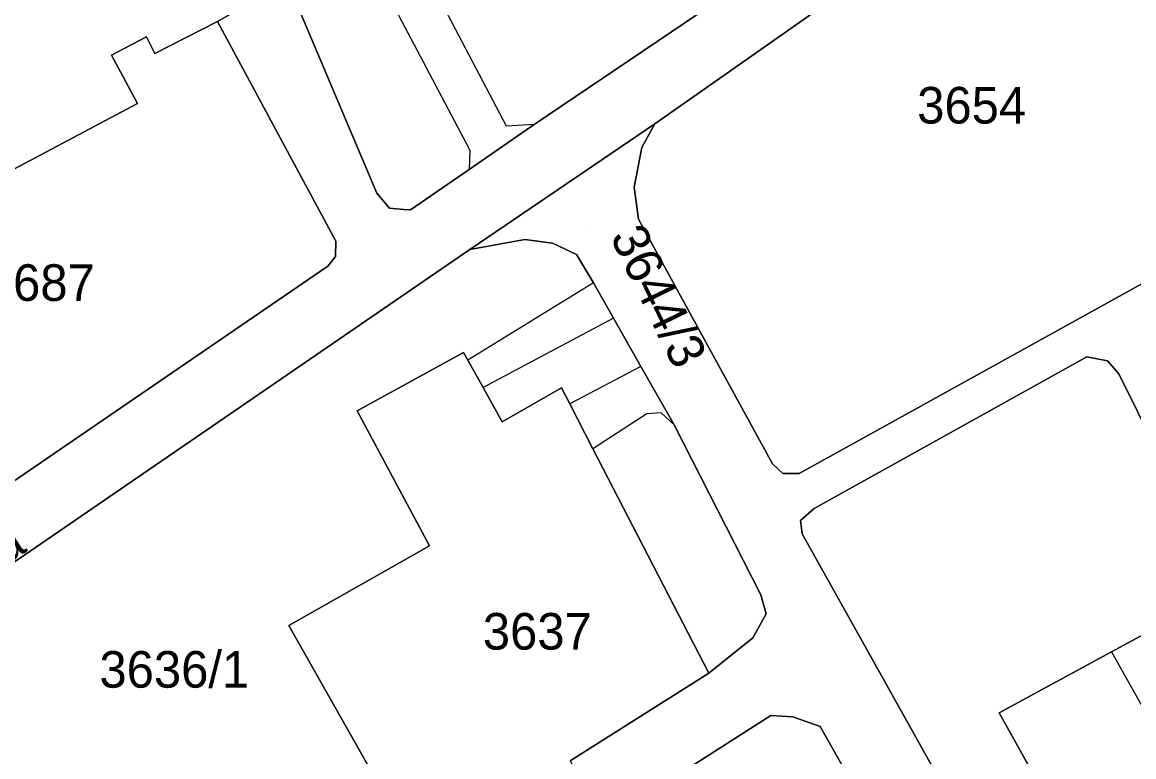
# Model space of a CAD drawing. Extents: x -262715 to -259381, y -1237238 to -1231182.
# Drawn here: x -261788.7 to -261728, y -1235759.3 to -1235719.2 of the extents above; entities that cross this region are included whole.
import ezdxf

# ---------------------------------------------------------------- set-up
doc = ezdxf.new("R2010")
doc.units = 0
for name, color, linetype in [('body_kn', 7, 'Continuous'), ('kladpar_druhypozemkov', 7, 'Continuous'), ('kladpar_hranice', 7, 'Continuous'), ('kladpar_parcelnecisla', 7, 'Continuous'), ('kladpar_plochy', 7, 'Continuous'), ('popisy', 7, 'Continuous'), ('zappar_hrandruhpozemk', 7, 'Continuous')]:
    doc.layers.add(name, color=color, linetype=linetype)

msp = doc.modelspace()

# ---------------------------------------------------------------- linework, layer by layer
at = {"layer": 'body_kn'}
for p, q in [((-261781.92, -1235719.95), (-261781.92, -1235719.95)), ((-261781.45, -1235720.86), (-261781.45, -1235720.86)), ((-261783.82, -1235720.96), (-261783.82, -1235720.96)), ((-261782.41, -1235723.59), (-261782.41, -1235723.59)), ((-261762.25, -1235724.84), (-261762.25, -1235724.84)), ((-261760.74, -1235724.75), (-261760.74, -1235724.75)), ((-261760.74, -1235724.75), (-261760.74, -1235724.75)), ((-261754.15, -1235724.7), (-261754.15, -1235724.7)), ((-261754.15, -1235724.7), (-261754.15, -1235724.7)), ((-261764.26, -1235726.15), (-261764.26, -1235726.15)), ((-261754.87, -1235726), (-261754.87, -1235726)), ((-261764.3, -1235727.21), (-261764.3, -1235727.21)), ((-261755.29, -1235728.17), (-261755.29, -1235728.17)), ((-261769.34, -1235728.5), (-261769.34, -1235728.5)), ((-261768.64, -1235729.32), (-261768.64, -1235729.32)), ((-261767.88, -1235729.38), (-261767.88, -1235729.38)), ((-261767.49, -1235729.41), (-261767.49, -1235729.41)), ((-261755.05, -1235729.92), (-261755.05, -1235729.92)), ((-261771.57, -1235731.11), (-261771.57, -1235731.11)), ((-261761.25, -1235731.03), (-261761.25, -1235731.03)), ((-261764.25, -1235731.57), (-261764.25, -1235731.57)), ((-261759.74, -1235731.22), (-261759.74, -1235731.22)), ((-261771.6, -1235731.95), (-261771.6, -1235731.95)), ((-261758.44, -1235731.84), (-261758.44, -1235731.84)), ((-261772.02, -1235732.49), (-261772.02, -1235732.49)), ((-261757.51, -1235733.39), (-261757.51, -1235733.39)), ((-261757.51, -1235733.39), (-261757.51, -1235733.39)), ((-261756.41, -1235735.32), (-261756.41, -1235735.32)), ((-261756.41, -1235735.32), (-261756.41, -1235735.32)), ((-261764.6, -1235737.19), (-261764.6, -1235737.19)), ((-261764.6, -1235737.19), (-261764.6, -1235737.19)), ((-261764.36, -1235737.62), (-261764.36, -1235737.62)), ((-261730.57, -1235737.43), (-261730.57, -1235737.43)), ((-261729.44, -1235737.66), (-261729.44, -1235737.66)), ((-261754.91, -1235737.97), (-261754.91, -1235737.97)), ((-261754.91, -1235737.97), (-261754.91, -1235737.97)), ((-261728.81, -1235738.36), (-261728.81, -1235738.36)), ((-261763.53, -1235739.11), (-261763.53, -1235739.11)), ((-261759.26, -1235739.13), (-261759.26, -1235739.13)), ((-261758.8, -1235740.01), (-261758.8, -1235740.01)), ((-261770.41, -1235740.39), (-261770.41, -1235740.39)), ((-261754.59, -1235740.55), (-261754.59, -1235740.55)), ((-261753.8, -1235740.5), (-261753.8, -1235740.5)), ((-261762.5, -1235740.98), (-261762.5, -1235740.98)), ((-261753.1, -1235741.15), (-261753.1, -1235741.15)), ((-261753.1, -1235741.15), (-261753.1, -1235741.15)), ((-261757.54, -1235742.46), (-261757.54, -1235742.46)), ((-261747.72, -1235743.29), (-261747.72, -1235743.29)), ((-261747.17, -1235743.8), (-261747.17, -1235743.8)), ((-261746.28, -1235743.8), (-261746.28, -1235743.8)), ((-261745.46, -1235745.72), (-261745.46, -1235745.72)), ((-261746.2, -1235746.37), (-261746.2, -1235746.37)), ((-261746.1, -1235747.11), (-261746.1, -1235747.11)), ((-261766.46, -1235747.76), (-261766.46, -1235747.76)), ((-261748.36, -1235750.44), (-261748.36, -1235750.44)), ((-261748.08, -1235751.48), (-261748.08, -1235751.48)), ((-261774.14, -1235752.11), (-261774.14, -1235752.11)), ((-261748.8, -1235752.78), (-261748.8, -1235752.78)), ((-261729.21, -1235753.55), (-261729.21, -1235753.55)), ((-261729.21, -1235753.55), (-261729.21, -1235753.55)), ((-261751.21, -1235754.71), (-261751.21, -1235754.71)), ((-261751.21, -1235754.71), (-261751.21, -1235754.71)), ((-261747.82, -1235757.03), (-261747.82, -1235757.03)), ((-261746.62, -1235757.1), (-261746.62, -1235757.1)), ((-261735.35, -1235756.88), (-261735.35, -1235756.88)), ((-261745.12, -1235757.63), (-261745.12, -1235757.63))]:
    msp.add_line(p, q, dxfattribs=at)
at = {"layer": 'kladpar_druhypozemkov'}
for p, q in [((-261736.65, -1235722.84), (-261736.65, -1235722.84)), ((-261757.99, -1235730.49), (-261757.99, -1235730.49)), ((-261787.49, -1235732.36), (-261787.49, -1235732.36)), ((-261759.9, -1235751.2), (-261759.9, -1235751.2)), ((-261780.12, -1235753.85), (-261780.12, -1235753.85))]:
    msp.add_line(p, q, dxfattribs=at)
at = {"layer": 'kladpar_hranice'}
for points in [[(-261717.12, -1235627), (-261717.4, -1235648.09), (-261717.59, -1235653.98), (-261717.84, -1235663.64), (-261718.13, -1235676.23), (-261719.51, -1235683.85), (-261721.57, -1235689.6), (-261724.9, -1235697.03), (-261727.66, -1235701.46), (-261730.28, -1235705), (-261736.14, -1235711.04), (-261740.93, -1235715.41), (-261754.15, -1235724.7), (-261764.25, -1235731.57), (-261797.34, -1235754.27)], [(-261789.32, -1235744.33), (-261772.02, -1235732.49), (-261771.6, -1235731.95), (-261771.57, -1235731.11), (-261778.03, -1235719.11), (-261774.4, -1235717.04), (-261773.56, -1235718.52), (-261769.34, -1235728.5), (-261768.64, -1235729.32), (-261767.88, -1235729.38), (-261767.49, -1235729.41), (-261764.3, -1235727.21), (-261760.74, -1235724.75), (-261750.28, -1235717.66), (-261746.09, -1235714.82), (-261743.34, -1235712.7), (-261738.81, -1235708.72), (-261732.7, -1235702.38), (-261728.83, -1235696.49), (-261726.07, -1235688.93)], [(-261730.28, -1235705), (-261722.76, -1235717.48), (-261717.28, -1235728.03), (-261724.17, -1235731.57), (-261746.28, -1235743.8), (-261747.17, -1235743.8), (-261747.72, -1235743.29), (-261755.05, -1235729.92), (-261755.29, -1235728.17), (-261754.87, -1235726), (-261754.15, -1235724.7), (-261740.93, -1235715.41), (-261736.14, -1235711.04), (-261730.28, -1235705)], [(-261791.19, -1235707.6), (-261790.03, -1235709.7), (-261784.69, -1235706.75), (-261783.79, -1235708.37), (-261780.06, -1235706.41), (-261779.54, -1235707.38), (-261774.4, -1235717.04), (-261778.03, -1235719.11), (-261781.45, -1235720.86), (-261781.92, -1235719.95), (-261783.82, -1235720.96), (-261782.41, -1235723.59), (-261790.93, -1235728.12), (-261799.6, -1235712.11), (-261791.19, -1235707.6)], [(-261778.03, -1235719.11), (-261771.57, -1235731.11), (-261771.6, -1235731.95), (-261772.02, -1235732.49), (-261789.32, -1235744.33), (-261790.33, -1235744.3), (-261790.91, -1235743.76), (-261806.68, -1235712.69), (-261805.76, -1235710.7), (-261804.47, -1235709.16), (-261802.05, -1235713.55), (-261799.6, -1235712.11), (-261790.93, -1235728.12), (-261782.41, -1235723.59), (-261783.82, -1235720.96), (-261781.92, -1235719.95), (-261781.45, -1235720.86), (-261778.03, -1235719.11)], [(-261750.28, -1235717.66), (-261760.74, -1235724.75), (-261764.3, -1235727.21), (-261767.49, -1235729.41), (-261767.88, -1235729.38), (-261768.64, -1235729.32), (-261769.34, -1235728.5), (-261773.56, -1235718.52)], [(-261758.78, -1235759.5), (-261751.21, -1235754.71), (-261748.8, -1235752.78), (-261748.08, -1235751.48), (-261748.36, -1235750.44), (-261753.1, -1235741.15), (-261754.91, -1235737.97), (-261756.41, -1235735.32), (-261757.51, -1235733.39), (-261758.44, -1235731.84), (-261759.74, -1235731.22), (-261761.25, -1235731.03), (-261764.25, -1235731.57), (-261754.15, -1235724.7)], [(-261754.15, -1235724.7), (-261754.87, -1235726), (-261755.29, -1235728.17), (-261755.05, -1235729.92), (-261747.72, -1235743.29), (-261747.17, -1235743.8), (-261746.28, -1235743.8), (-261724.17, -1235731.57), (-261717.28, -1235728.03), (-261716.2, -1235730.01), (-261723.1, -1235733.74), (-261726.07, -1235735.35), (-261726.53, -1235736.18), (-261726.41, -1235736.84), (-261722.55, -1235743.22), (-261725.61, -1235744.82), (-261728.81, -1235738.36), (-261729.44, -1235737.66), (-261730.57, -1235737.43), (-261745.46, -1235745.72), (-261746.2, -1235746.37), (-261746.1, -1235747.11), (-261697.33, -1235834.41)], [(-261797.34, -1235754.27), (-261764.25, -1235731.57), (-261761.25, -1235731.03), (-261759.74, -1235731.22), (-261758.44, -1235731.84), (-261757.51, -1235733.39), (-261756.41, -1235735.32), (-261754.91, -1235737.97), (-261753.1, -1235741.15), (-261748.36, -1235750.44), (-261748.08, -1235751.48), (-261748.8, -1235752.78), (-261751.21, -1235754.71)], [(-261751.21, -1235754.71), (-261757.54, -1235742.46), (-261758.8, -1235740.01), (-261759.26, -1235739.13), (-261762.5, -1235740.98), (-261763.53, -1235739.11), (-261764.36, -1235737.62), (-261764.6, -1235737.19), (-261770.41, -1235740.39), (-261766.46, -1235747.76), (-261774.14, -1235752.11), (-261765.37, -1235767.62)], [(-261764.6, -1235737.19), (-261764.36, -1235737.62), (-261763.53, -1235739.11), (-261762.5, -1235740.98), (-261759.26, -1235739.13), (-261758.8, -1235740.01), (-261757.54, -1235742.46), (-261751.21, -1235754.71), (-261758.78, -1235759.5), (-261756.9, -1235762.83), (-261765.37, -1235767.62), (-261774.14, -1235752.11), (-261766.46, -1235747.76), (-261770.41, -1235740.39), (-261764.6, -1235737.19)], [(-261725.61, -1235744.82), (-261727.44, -1235752.59), (-261729.21, -1235753.55), (-261735.35, -1235756.88), (-261699.94, -1235820.45), (-261693.78, -1235817.07), (-261687.54, -1235813.73), (-261684.67, -1235818.85), (-261683.91, -1235820.21), (-261680.97, -1235825.29), (-261680.7, -1235826.01), (-261681.15, -1235826.78), (-261695.73, -1235835.01), (-261696.66, -1235835.19), (-261697.33, -1235834.41), (-261746.1, -1235747.11), (-261746.2, -1235746.37), (-261745.46, -1235745.72), (-261730.57, -1235737.43), (-261729.44, -1235737.66), (-261728.81, -1235738.36), (-261725.61, -1235744.82)], [(-261699.94, -1235820.45), (-261735.35, -1235756.88), (-261729.21, -1235753.55), (-261727.44, -1235752.59), (-261725.61, -1235744.82), (-261722.55, -1235743.22), (-261719.9, -1235741.83), (-261711.44, -1235758.07), (-261706.32, -1235755.4), (-261707.75, -1235752.48), (-261705.09, -1235751.27), (-261696.75, -1235746.72), (-261697.71, -1235744.96), (-261692.22, -1235742.13)], [(-261765.37, -1235767.62), (-261756.9, -1235762.83), (-261747.82, -1235757.03), (-261746.62, -1235757.1), (-261745.12, -1235757.63), (-261691.44, -1235852.69), (-261691.06, -1235854.65), (-261691.29, -1235856.33), (-261693.25, -1235858.5), (-261692.1, -1235852.85), (-261741.24, -1235766.77), (-261759.23, -1235777.31), (-261765.37, -1235767.62)], [(-261691.44, -1235852.69), (-261745.12, -1235757.63), (-261746.62, -1235757.1), (-261747.82, -1235757.03), (-261756.9, -1235762.83)]]:
    msp.add_lwpolyline(points, dxfattribs=at)
at = {"layer": 'kladpar_plochy'}
for points in [[(-261717.12, -1235627), (-261717.4, -1235648.09), (-261717.59, -1235653.98), (-261717.84, -1235663.64), (-261718.13, -1235676.23), (-261719.51, -1235683.85), (-261721.57, -1235689.6), (-261724.9, -1235697.03), (-261727.66, -1235701.46), (-261730.28, -1235705), (-261736.14, -1235711.04), (-261740.93, -1235715.41), (-261754.15, -1235724.7), (-261764.25, -1235731.57), (-261797.34, -1235754.27)], [(-261789.32, -1235744.33), (-261772.02, -1235732.49), (-261771.6, -1235731.95), (-261771.57, -1235731.11), (-261778.03, -1235719.11), (-261774.4, -1235717.04), (-261773.56, -1235718.52), (-261769.34, -1235728.5), (-261768.64, -1235729.32), (-261767.88, -1235729.38), (-261767.49, -1235729.41), (-261764.3, -1235727.21), (-261760.74, -1235724.75), (-261750.28, -1235717.66), (-261746.09, -1235714.82), (-261743.34, -1235712.7), (-261738.81, -1235708.72), (-261732.7, -1235702.38), (-261728.83, -1235696.49), (-261726.07, -1235688.93)], [(-261750.28, -1235717.66), (-261760.74, -1235724.75), (-261764.3, -1235727.21), (-261767.49, -1235729.41), (-261767.88, -1235729.38), (-261768.64, -1235729.32), (-261769.34, -1235728.5), (-261773.56, -1235718.52)], [(-261758.78, -1235759.5), (-261751.21, -1235754.71), (-261748.8, -1235752.78), (-261748.08, -1235751.48), (-261748.36, -1235750.44), (-261753.1, -1235741.15), (-261754.91, -1235737.97), (-261756.41, -1235735.32), (-261757.51, -1235733.39), (-261758.44, -1235731.84), (-261759.74, -1235731.22), (-261761.25, -1235731.03), (-261764.25, -1235731.57), (-261754.15, -1235724.7), (-261754.87, -1235726), (-261755.29, -1235728.17), (-261755.05, -1235729.92), (-261747.72, -1235743.29), (-261747.17, -1235743.8), (-261746.28, -1235743.8), (-261724.17, -1235731.57)], [(-261797.34, -1235754.27), (-261764.25, -1235731.57), (-261761.25, -1235731.03), (-261759.74, -1235731.22), (-261758.44, -1235731.84), (-261757.51, -1235733.39), (-261756.41, -1235735.32), (-261754.91, -1235737.97), (-261753.1, -1235741.15), (-261748.36, -1235750.44), (-261748.08, -1235751.48), (-261748.8, -1235752.78), (-261751.21, -1235754.71), (-261757.54, -1235742.46), (-261758.8, -1235740.01), (-261759.26, -1235739.13), (-261762.5, -1235740.98), (-261763.53, -1235739.11), (-261764.36, -1235737.62), (-261764.6, -1235737.19), (-261770.41, -1235740.39), (-261766.46, -1235747.76), (-261774.14, -1235752.11), (-261765.37, -1235767.62)], [(-261725.61, -1235744.82), (-261728.81, -1235738.36), (-261729.44, -1235737.66), (-261730.57, -1235737.43), (-261745.46, -1235745.72), (-261746.2, -1235746.37), (-261746.1, -1235747.11), (-261697.33, -1235834.41)], [(-261699.94, -1235820.45), (-261735.35, -1235756.88), (-261729.21, -1235753.55), (-261727.44, -1235752.59), (-261725.61, -1235744.82), (-261722.55, -1235743.22), (-261719.9, -1235741.83), (-261711.44, -1235758.07), (-261706.32, -1235755.4), (-261707.75, -1235752.48), (-261705.09, -1235751.27), (-261696.75, -1235746.72), (-261697.71, -1235744.96), (-261692.22, -1235742.13), (-261691.31, -1235743.76), (-261688.29, -1235749.41), (-261684.3, -1235756.86), (-261675.54, -1235752.17), (-261676.2, -1235750.94), (-261674.29, -1235749.92), (-261673.63, -1235751.15), (-261657.74, -1235742.65), (-261645.58, -1235763.47)], [(-261691.44, -1235852.69), (-261745.12, -1235757.63), (-261746.62, -1235757.1), (-261747.82, -1235757.03), (-261756.9, -1235762.83)]]:
    msp.add_lwpolyline(points, dxfattribs=at)
for points in [[(-261730.28, -1235705), (-261722.76, -1235717.48), (-261717.28, -1235728.03), (-261724.17, -1235731.57), (-261746.28, -1235743.8), (-261747.17, -1235743.8), (-261747.72, -1235743.29), (-261755.05, -1235729.92), (-261755.29, -1235728.17), (-261754.87, -1235726), (-261754.15, -1235724.7), (-261740.93, -1235715.41), (-261736.14, -1235711.04)], [(-261791.19, -1235707.6), (-261790.03, -1235709.7), (-261784.69, -1235706.75), (-261783.79, -1235708.37), (-261780.06, -1235706.41), (-261779.54, -1235707.38), (-261774.4, -1235717.04), (-261778.03, -1235719.11), (-261781.45, -1235720.86), (-261781.92, -1235719.95), (-261783.82, -1235720.96), (-261782.41, -1235723.59), (-261790.93, -1235728.12), (-261799.6, -1235712.11)], [(-261778.03, -1235719.11), (-261771.57, -1235731.11), (-261771.6, -1235731.95), (-261772.02, -1235732.49), (-261789.32, -1235744.33), (-261790.33, -1235744.3), (-261790.91, -1235743.76), (-261806.68, -1235712.69), (-261805.76, -1235710.7), (-261804.47, -1235709.16), (-261802.05, -1235713.55), (-261799.6, -1235712.11), (-261790.93, -1235728.12), (-261782.41, -1235723.59), (-261783.82, -1235720.96), (-261781.92, -1235719.95), (-261781.45, -1235720.86)], [(-261764.6, -1235737.19), (-261764.36, -1235737.62), (-261763.53, -1235739.11), (-261762.5, -1235740.98), (-261759.26, -1235739.13), (-261758.8, -1235740.01), (-261757.54, -1235742.46), (-261751.21, -1235754.71), (-261758.78, -1235759.5), (-261756.9, -1235762.83), (-261765.37, -1235767.62), (-261774.14, -1235752.11), (-261766.46, -1235747.76), (-261770.41, -1235740.39)], [(-261725.61, -1235744.82), (-261727.44, -1235752.59), (-261729.21, -1235753.55), (-261735.35, -1235756.88), (-261699.94, -1235820.45), (-261693.78, -1235817.07), (-261687.54, -1235813.73), (-261684.67, -1235818.85), (-261683.91, -1235820.21), (-261680.97, -1235825.29), (-261680.7, -1235826.01), (-261681.15, -1235826.78), (-261695.73, -1235835.01), (-261696.66, -1235835.19), (-261697.33, -1235834.41), (-261746.1, -1235747.11), (-261746.2, -1235746.37), (-261745.46, -1235745.72), (-261730.57, -1235737.43), (-261729.44, -1235737.66), (-261728.81, -1235738.36)], [(-261765.37, -1235767.62), (-261756.9, -1235762.83), (-261747.82, -1235757.03), (-261746.62, -1235757.1), (-261745.12, -1235757.63), (-261691.44, -1235852.69), (-261691.06, -1235854.65), (-261691.29, -1235856.33), (-261693.25, -1235858.5), (-261692.1, -1235852.85), (-261741.24, -1235766.77), (-261759.23, -1235777.31)]]:
    msp.add_lwpolyline(points, close=True, dxfattribs=at)
at = {"layer": 'zappar_hrandruhpozemk'}
for p, q in [((-261762.25, -1235724.84), (-261767.34, -1235715.16)), ((-261769.44, -1235716.3), (-261764.26, -1235726.15)), ((-261760.74, -1235724.75), (-261762.25, -1235724.84)), ((-261764.26, -1235726.15), (-261764.3, -1235727.21)), ((-261757.51, -1235733.39), (-261764.36, -1235737.62)), ((-261756.41, -1235735.32), (-261763.53, -1235739.11)), ((-261754.91, -1235737.97), (-261758.8, -1235740.01)), ((-261729.21, -1235753.55), (-261693.78, -1235817.07))]:
    msp.add_line(p, q, dxfattribs=at)
msp.add_lwpolyline([(-261753.1, -1235741.15), (-261753.8, -1235740.5), (-261754.59, -1235740.55), (-261757.54, -1235742.46)], dxfattribs=at)

# ---------------------------------------------------------------- texts
at = {"layer": 'kladpar_parcelnecisla'}
for s, p in [('3654', (-261739.827, -1235724.69)), ('3687', (-261790.687, -1235734.38)), ('3637', (-261763.547, -1235753.43)), ('3636/1', (-261784.485, -1235755.51))]:
    msp.add_text(s, height=2, dxfattribs=at).set_placement(p)
msp.add_text('3644/3', height=2, rotation=296, dxfattribs=at).set_placement((-261756.625, -1235730.865))
at = {"layer": 'popisy'}
msp.add_text('Maïarská', height=2, rotation=33, dxfattribs=at).set_placement((-261797.603, -1235754.016))

doc.saveas('drawing.dxf')
